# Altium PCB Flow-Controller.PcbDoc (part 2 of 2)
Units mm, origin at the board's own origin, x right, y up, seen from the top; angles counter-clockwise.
Board outline 85 x 90 mm, 2 copper layers (Top Layer, Bottom Layer), stack 1.571 mm thick; 113 components, 85 nets, 341 pads, 150 vias.
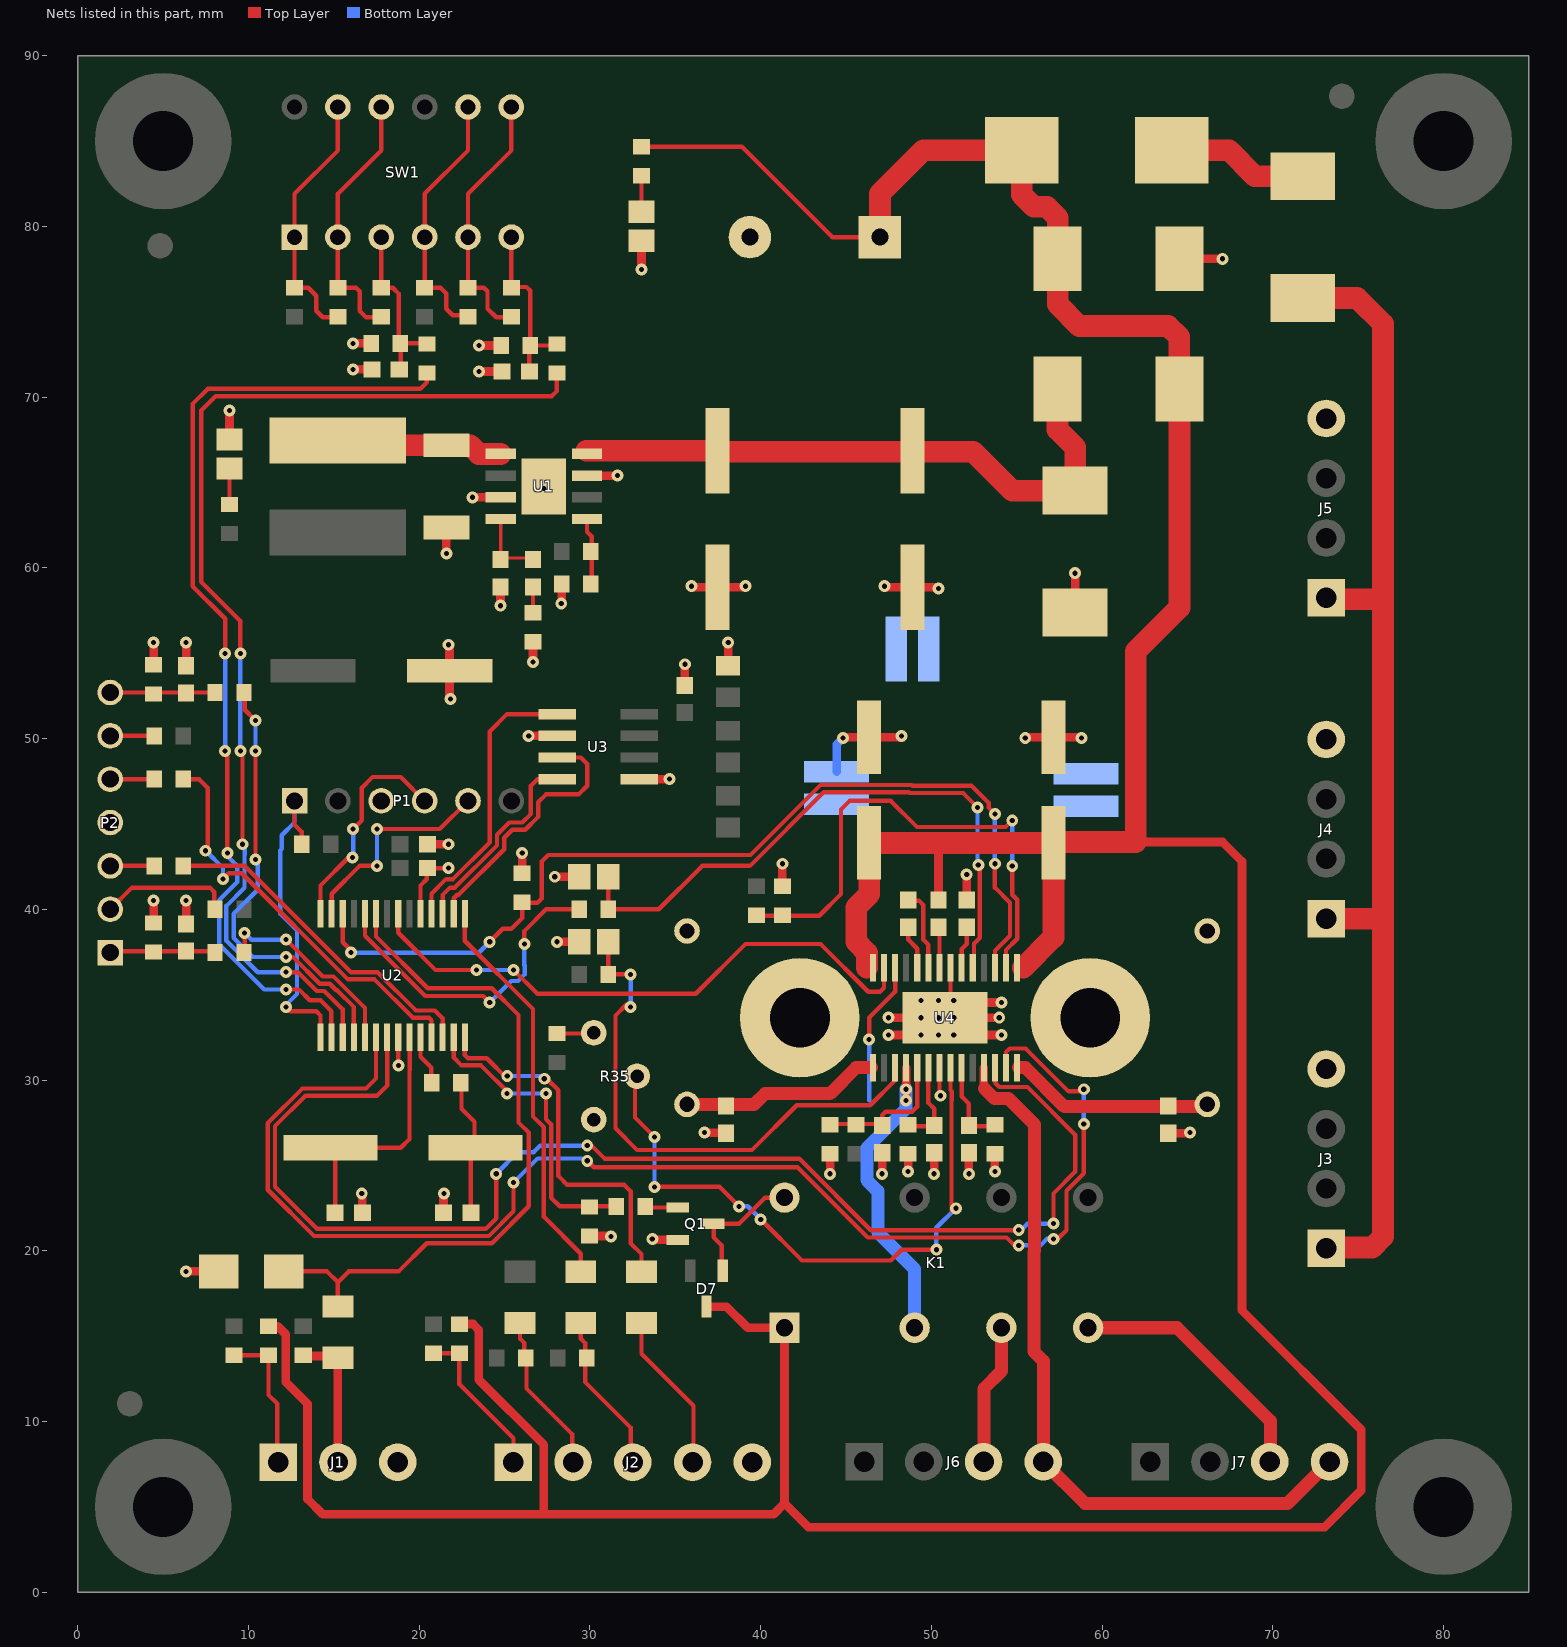
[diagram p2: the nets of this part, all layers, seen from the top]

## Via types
v1: diameter 0.7, hole 0.3, Top Layer to Bottom Layer, tented both sides, 150 vias

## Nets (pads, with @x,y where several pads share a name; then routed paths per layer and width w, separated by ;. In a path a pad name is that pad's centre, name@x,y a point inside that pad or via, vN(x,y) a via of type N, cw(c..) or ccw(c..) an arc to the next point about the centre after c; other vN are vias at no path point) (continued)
GND1: C1.2 C16.2 C17.2 C21.2 D4.2 HS1.1 HS1.2 J3.4 J4.4 J5.4 LED1.1 LK1.1 LK2.1 LK3.1 U4.21 U4.29 | length 39.2
  Top Layer w0.254: U4.29@51.125,33.853 51.125,34.488 U4.21@51.125,36.572
  Top Layer w0.508: v1(33.02,77.47) LED1.1@33.02,79.16 ; v1(44.831,50.038) 44.883,50.09 C16.2@46.355,50.09 48.185,50.09 v1(48.26,50.165) ; v1(47.498,32.639) 48.387,32.639 v1(49.403,33.655) ; v1(47.498,33.655) v1(49.403,33.655) ; v1(49.403,32.639) 49.784,32.639 U4.29@50.8,33.655 ; v1(49.403,34.671) 49.784,34.671 50.102,34.353 U4.29@50.8,33.655 ; v1(50.419,32.639) 50.8,33.02 U4.29@50.8,33.147 ; v1(50.419,34.671) 50.8,34.29 U4.29@50.8,34.163 ; v1(51.308,32.639) U4.29@50.8,33.147 ; v1(51.308,34.671) 51.125,34.488 U4.29@50.8,34.163 ; C21.2@52.07,40.551 v1(52.07,42.037) ; v1(53.975,33.655) U4.29@51.689,33.655 ; v1(54.102,32.639) 52.705,32.639 U4.29@51.689,33.655 ; v1(54.102,34.544) 52.578,34.544 U4.29@51.689,33.655 ; v1(55.499,50.038) 55.551,50.09 C17.2@57.15,50.09 58.749,50.09 v1(58.801,50.038) ; D4.2@64.53,78.105 v1(67.056,78.105) ; v1(49.403,33.655) v1(50.419,33.655) U4.29@50.8,33.655 ; U4.29@50.8,33.147 U4.29@50.8,33.655 ; U4.29@50.8,33.655 U4.29@50.8,34.163 ; U4.29@50.8,33.655 v1(51.308,33.655) U4.29@51.689,33.655
  Bottom Layer w0.508: LK2.1@44.45,48.069 44.45,49.657 v1(44.831,50.038)
GND2: C2.2 C3.2 C4.2 C6.2 C7.2 C8.2 C9.2 C10.2 C11.2 C12.2 C13.2 C14.2 C15.2 C20.2 C24.2 C25.2 C26.2 C27.2 D5.2 D6.2 J1.3 J2.5 LED2.1 LK1.2 P1.3 P2.4 Q1.2 R4.2 R5.2 R13.2 R30.2 R31.2 R32.2 R35.3 R36.2 R38.2 R41.2 R42.2 R48.2 R49.2 R54.2 U1.3 U1.7 U1.9 U2.8 U2.19 U3.2 U3.5 U4.7 U4.26 Z1.2 | length 74.6
  Top Layer w0.254: U2.8@18.774,32.512 18.774,30.883 v1(18.796,30.861) ; U2.19@20.074,39.751 20.074,41.394 20.447,41.767 20.447,42.291 20.574,42.418 v1(21.717,42.418) ; v1(46.355,32.385) 46.355,33.655 47.875,35.175 U4.26@47.875,36.572 ; U4.7@50.475,30.73 50.475,29.154 v1(50.546,29.083)
  Top Layer w0.508: R32.2@4.445,39.204 v1(4.445,40.513) ; R31.2@4.445,54.317 v1(4.445,55.626) ; v1(6.35,18.796) 6.352,18.794 Z1.2@8.255,18.794 ; C14.2@6.35,39.154 v1(6.35,40.513) ; C13.2@6.35,54.267 v1(6.35,55.626) ; LED2.1@8.89,67.525 v1(8.89,69.215) ; v1(16.129,71.628) C26.2@17.234,71.628 ; v1(16.129,73.152) R49.2@17.184,73.152 ; v1(16.637,23.368) 16.675,23.33 C10.2@16.675,22.225 ; C12.2@20.485,43.815 v1(21.717,43.815) ; C9.2@21.425,22.225 21.425,23.33 v1(21.463,23.368) ; v1(21.59,60.833) D6.2@21.59,62.357 ; v1(21.717,55.499) 21.78,55.436 C4.2@21.78,53.975 21.78,52.388 v1(21.844,52.324) ; v1(23.114,64.135) U1.3@24.778,64.135 ; v1(23.495,71.501) C27.2@24.854,71.501 ; v1(23.495,73.025) R54.2@24.804,73.025 ; v1(24.765,57.785) C6.2@24.765,58.89 ; R13.2@26.035,42.125 v1(26.035,43.307) ; v1(26.416,50.165) U3.2@28.08,50.165 ; v1(26.67,54.483) R4.2@26.67,55.665 ; v1(27.305,64.643) U1.9@27.305,64.77 ; v1(27.94,41.91) C7.2@29.376,41.91 ; v1(28.067,38.1) C8.2@29.376,38.1 ; v1(28.321,57.912) 28.36,57.951 R5.2@28.36,59.055 ; U1.7@29.832,65.405 v1(31.623,65.405) ; R48.2@29.972,20.867 31.203,20.867 v1(31.242,20.828) ; U3.5@32.88,47.625 v1(34.671,47.625) ; v1(33.655,20.701) 33.716,20.64 Q1.2@35.145,20.64 ; C15.2@35.56,53.124 v1(35.56,54.356) ; v1(35.941,58.928) 36.004,58.865 C3.2@37.465,58.865 39.053,58.865 v1(39.116,58.928) ; R30.2@38.1,54.265 v1(38.1,55.626) ; R36.2@41.275,41.363 v1(41.275,42.672) ; v1(44.069,24.511) R38.2@44.069,25.693 ; v1(47.117,24.511) C20.2@47.117,25.743 ; v1(47.244,58.928) 47.307,58.865 C2.2@48.895,58.865 50.355,58.865 v1(50.419,58.801) ; v1(48.641,24.638) R41.2@48.641,25.693 ; v1(50.165,24.511) C24.2@50.165,25.743 ; v1(52.197,24.511) C25.2@52.197,25.743 ; v1(53.721,24.638) R42.2@53.721,25.693 ; D5.2@58.42,57.39 v1(58.42,59.69)
  Bottom Layer w0.254: 46.355,28.829 v1(46.355,32.385)
GND3: C22.2 LK2.2 R39.1 | length 1.3
  Top Layer w0.508: v1(36.703,26.924) 37.935,26.924 C22.2@37.973,26.886
GND4: C23.2 LK3.2 R40.1 | length 1.3
  Top Layer w0.508: C23.2@63.881,26.886 65.113,26.886 v1(65.151,26.924)
GREEN: J6.4 J7.4 U4.11 | length 44
  Top Layer w0.254: J6.4@56.515,7.62 J6.4@56.515,7.645
  Top Layer w0.508: 53.075,29.348 U4.11@53.075,30.73
  Top Layer w0.762: 53.103,29.508 53.698,28.913 54.53,28.913 56.05,27.393 56.05,19.978 56.009,19.937 56.009,14.095 56.558,13.546 J6.4@56.558,7.645 58.996,5.207 70.866,5.207 J7.4@73.279,7.62
GREEN_LED: R27.1 U2.12 | length 20
  Top Layer w0.254: R27.1@6.223,42.545 9.779,42.545 16.002,36.322 17.561,36.322 19.806,34.077 20.914,34.077 21.374,33.617 U2.12@21.374,32.512
M_0: R24.1 U2.4 | length 25.9
  Top Layer w0.254: R24.1@9.779,52.832 9.779,51.689 v1(10.414,51.054) ; v1(10.414,42.926) v1(10.414,49.276) ; v1(12.192,37.211) 12.608,37.211 14.175,35.644 14.765,35.644 15.148,35.26 15.194,35.26 16.174,34.28 U2.4@16.174,32.512
  Bottom Layer w0.254: v1(10.414,42.926) 10.541,42.799 10.541,41.148 9.132,39.739 9.132,38.34 10.261,37.211 v1(12.192,37.211) ; v1(10.414,49.276) v1(10.414,51.054)
M_1: R29.1 U2.5 | length 11.7
  Top Layer w0.254: R29.1@9.779,37.465 v1(9.779,38.608) ; v1(12.192,38.227) 14.351,36.068 14.986,36.068 16.824,34.23 U2.5@16.824,32.512
  Bottom Layer w0.254: v1(9.779,38.608) 10.16,38.227 v1(12.192,38.227)
MCLR: P1.1 R6.2 U2.1 | length 19.3
  Top Layer w0.254: v1(12.192,34.29) 12.448,34.034 13.97,34.034 14.224,33.78 U2.1@14.224,32.512 ; P1.1@12.7,46.355 12.7,44.958 13.12,44.538 R6.2@13.12,43.815
  Bottom Layer w0.254: v1(12.192,34.29) 12.192,34.391 12.839,35.038 12.839,38.766 11.854,39.751 11.854,43.451 11.95,43.547 11.95,44.335 12.7,45.085 P1.1@12.7,46.355
MS_1: U2.6 U4.13 | length 82.3
  Top Layer w0.254: U2.6@17.474,32.512 17.474,30.09 16.891,29.507 13.159,29.507 11.133,27.481 11.133,23.573 13.835,20.871 24.081,20.871 25.527,22.317 v1(25.527,24.003) ; v1(29.845,25.273) 30.226,24.892 42.164,24.892 46.271,20.785 54.399,20.785 54.864,20.32 v1(55.118,20.32) ; U4.13@54.375,30.73 54.375,31.642 54.588,31.855 55.521,31.855 58.039,29.337 58.801,29.337 v1(58.928,29.464) ; v1(57.15,20.701) 57.404,20.701 57.912,21.209 57.912,23.521 58.928,24.537 v1(58.928,27.432)
  Bottom Layer w0.254: v1(25.527,24.003) 26.936,25.412 29.706,25.412 v1(29.845,25.273) ; v1(55.118,20.32) 56.388,20.32 56.769,20.701 v1(57.15,20.701) ; v1(58.928,27.432) v1(58.928,29.464)
MS_2: U2.7 U4.12 | length 78
  Top Layer w0.254: U2.7@18.124,32.512 18.124,29.681 17.526,29.083 13.335,29.083 11.557,27.305 11.557,23.749 14.011,21.295 23.906,21.295 24.511,21.9 v1(24.511,24.511) ; v1(29.845,26.162) 30.099,26.162 30.861,25.4 42.256,25.4 46.447,21.209 v1(55.118,21.209) ; 53.725,29.845 53.979,29.591 55.626,29.591 58.42,26.797 58.42,24.629 57.15,23.359 v1(57.15,21.59)
  Bottom Layer w0.254: v1(24.511,24.511) 25.781,25.781 26.705,25.781 27.086,26.162 v1(29.845,26.162) ; v1(55.118,21.209) 55.245,21.209 55.626,21.59 v1(57.15,21.59)
NetC5_1: C5.1 C6.1 U1.4 | length 4.2
  Top Layer w0.2: U1.4@24.778,62.865 24.778,60.592 24.791,60.579 C5.1@26.67,60.579
NetC5_2: C5.2 R4.1 | length 1.4
  Top Layer w0.254: R4.1@26.67,57.531 C5.2@26.67,58.89
NetC7_1: C7.1 R11.2 U4.19 | length 36.8
  Top Layer w0.2: 52.483,38.008 52.815,38.339
  Top Layer w0.254: C7.1@31.076,41.822 R11.2@31.076,40.005 34.036,40.005 36.576,42.545 39.37,42.545 43.688,46.863 48.676,46.863 48.719,46.82 51.859,46.82 v1(52.705,45.974) ; U4.19@52.425,36.572 52.494,36.641 52.494,37.98 52.842,38.328 v1@52.842,42.505 ; v1(52.749,42.589) v1@52.832,42.505
  Bottom Layer w0.254: v1(52.705,45.974) 52.705,42.632 v1(52.749,42.589)
NetC8_1: C8.1 R12.2 U4.3 | length 32.4
  Top Layer w0.254: R12.2@30.861,36.195 R12.2@31.076,36.195 ; C8.1@31.076,38.061 R12.2@31.076,36.195 ; v1(32.385,34.29) 32.258,34.417 32.131,34.417 31.496,33.782 31.496,27.178 32.766,25.908 39.497,25.908 42.121,28.532 46.425,28.532 47.875,29.982 U4.3@47.875,30.73 ; v1(32.385,36.195) R12.2@31.076,36.195
  Bottom Layer w0.254: v1(32.385,34.29) v1(32.385,36.195)
NetC9_1: C9.1 R14.1 X1.1 | length 7.9
  Top Layer w0.254: R14.1@22.479,29.845 22.479,28.321 23.241,27.559 X1.1@23.241,26.035 ; C9.1@23.025,22.225 X1.1@23.025,25.997
NetC10_1: C10.1 U2.9 X1.2 | length 14.1
  Top Layer w0.254: C10.1@15.075,22.225 X1.2@15.075,25.819 ; X1.2@15.113,26.035 18.923,26.035 19.431,26.543 19.431,30.562 19.443,30.574 19.443,32.493 U2.9@19.424,32.512
NetC13_1: C13.1 P2.7 R24.2 R31.1 | length 6.1
  Top Layer w0.254: P2.7@1.905,52.705 R24.2@8.001,52.705
NetC14_1: C14.1 P2.1 R29.2 R32.1 | length 6.2
  Top Layer w0.254: P2.1@1.994,37.554 C14.1@6.35,37.554 R29.2@8.166,37.554
NetC18_2: C18.2 U4.22 | length 2.4
  Top Layer w0.254: U4.22@50.475,36.572 C18.2@50.475,38.933
NetC19_1: C19.1 U4.24 | length 2.5
  Top Layer w0.254: C19.1@48.641,38.862 48.641,38.227 49.175,37.693 U4.24@49.175,36.572
NetC19_2: C19.2 U4.23 | length 4.7
  Top Layer w0.254: C19.2@48.768,40.513 49.276,40.513 49.53,40.259 49.53,38.227 49.825,37.932 U4.23@49.825,36.572
NetC20_1: C20.1 R37.2 R38.1 U4.5 | length 8.1
  Top Layer w0.254: R38.1@44.069,27.432 47.117,27.432 47.117,27.94 47.32,28.143 48.838,28.143 48.841,28.14 ; 48.816,28.14 48.841,28.14 ; U4.5@49.175,30.73 49.175,28.445 48.87,28.14 48.841,28.14
NetC21_1: C21.1 U4.20 | length 2.4
  Top Layer w0.254: U4.20@51.775,36.572 51.775,37.678 52.07,37.973 C21.1@52.07,38.862
NetC22_1: C22.1 R39.2 U4.1 | length 11.7
  Top Layer w0.762: R39.2@35.687,28.575 39.624,28.575 40.259,29.21 44.069,29.21 45.593,30.734 U4.1@46.482,30.734
NetC23_1: C23.1 R40.2 U4.14 | length 12.1
  Top Layer w0.762: U4.14@55.104,30.734 55.499,30.734 57.785,28.448 66.04,28.448 R40.2@66.167,28.575
NetC24_1: C24.1 R41.1 U4.6 | length 5.1
  Top Layer w0.254: R41.1@48.641,27.432 48.768,27.305 50.165,27.305 C24.1@50.165,27.343 50.165,28.321 49.825,28.661 U4.6@49.825,30.73
NetC25_1: C25.1 R42.1 U4.9 | length 5.2
  Top Layer w0.254: U4.9@51.775,30.73 51.775,29.032 52.197,28.61 C25.1@52.197,27.343 52.197,27.305 53.594,27.305 R42.1@53.721,27.432
NetC26_1: C26.1 R45.2 R47.2 R49.1 SW1.3 | length 10.2
  Top Layer w0.254: SW1.3@17.78,79.375 R45.2@17.78,76.415 18.454,76.415 18.796,76.073 18.796,73.152 18.923,73.025 C26.1@18.923,71.628 ; R49.1@18.884,73.152 R47.2@20.447,73.152
NetC27_1: C27.1 R52.2 R53.2 R54.1 SW1.6 | length 9.7
  Top Layer w0.254: R52.2@25.4,76.415 SW1.6@25.4,79.121 ; R52.2@25.527,76.454 26.289,76.454 26.504,76.239 R54.1@26.504,73.025 R53.2@27.813,73.025 ; C27.1@26.454,71.501 R54.1@26.454,72.936
NetD1_1: D1.1 D3.1 | length 8.4
  Top Layer w1.27: D3.1@64.008,84.455 D3.1@64.09,84.455 67.437,84.455 68.947,82.945 D1.1@71.755,82.945
NetD6_1: D6.1 L1.1 U1.1 | length 9.7
  Top Layer w1.27: L1.1@15.24,67.183 D6.1@21.59,67.183 22.987,67.183 23.495,66.675 U1.1@24.778,66.675
NetD7_1: D7.1 K1.16 Q1.3 | length 7.8
  Top Layer w0.254: D7.1@37.719,18.796 37.719,20.32 37.245,20.794 Q1.3@37.245,21.59 38.735,21.59 40.259,23.114 K1.16@41.402,23.114
NetJ1_1: J1.1 R8.2 R9.2 | length 8.5
  Top Layer w0.254: R8.2@9.183,13.882 R9.2@11.176,13.882 11.176,11.557 11.684,11.049 J1.1@11.684,7.62
NetJ1_2: J1.2 R7.2 R10.2 | length 8.1
  Top Layer w0.508: R7.2@13.208,13.843 14.986,13.843 15.24,13.589 J1.2@15.24,7.62
NetJ2_1: J2.1 R17.2 R18.2 | length 9.7
  Top Layer w0.254: R17.2@20.828,14.009 R18.2@22.352,14.009 R18.2@22.694,14.009 ; R18.2@22.352,13.97 22.352,12.192 25.527,9.017 J2.1@25.527,7.493
NetJ2_2: J2.2 R16.2 R19.2 | length 9.5
  Top Layer w0.254: R19.2@25.908,15.772 25.908,14.859 26.162,14.605 26.162,13.716 26.289,13.589 26.289,11.938 28.956,9.271 J2.2@28.956,7.493
NetJ2_3: J2.3 R15.2 R20.2 | length 9.4
  Top Layer w0.254: R20.2@29.464,15.772 29.464,14.859 29.718,14.605 29.718,12.319 32.385,9.652 J2.3@32.385,7.62
NetJ2_4: J2.4 R21.2 | length 9.4
  Top Layer w0.254: R21.2@33.02,15.772 33.02,13.97 36.068,10.922 J2.4@36.068,7.62
NetLED1_2: LED1.2 R1.2 | length 2.1
  Top Layer w0.254: LED1.2@33.02,80.86 R1.2@33.02,82.931
NetLED2_2: LED2.2 R2.2 | length 1.9
  Top Layer w0.254: R2.2@8.89,63.715 LED2.2@8.89,65.659
NetP2_2: P2.2 R26.2 | length 7.7
  Top Layer w0.254: P2.2@1.905,40.005 3.175,41.275 7.747,41.275 8.001,41.021 R26.2@8.001,40.005
NetP2_3: P2.3 R27.2 | length 2.5
  Top Layer w0.254: P2.3@2.032,42.545 R27.2@4.484,42.545
NetP2_5: P2.5 R28.2 | length 2.5
  Top Layer w0.254: P2.5@2.032,47.625 R28.2@4.484,47.625
NetP2_6: P2.6 R25.2 | length 2.3
  Top Layer w0.254: P2.6@2.159,50.165 R25.2@4.484,50.165
NetQ1_1: Q1.1 R46.2 | length 1.8
  Top Layer w0.254: R46.2@33.335,22.54 Q1.1@35.145,22.54
NetR3_2: R3.2 R5.1 U1.5 | length 4
  Top Layer w0.254: U1.5@29.832,62.865 29.832,62.116 30.099,61.849 R5.1@30.099,58.928
NetR14_2: R14.2 U2.10 | length 2.9
  Top Layer w0.254: U2.10@20.074,32.512 20.074,31.361 20.701,30.734 R14.2@20.701,29.845
NetR33_2: R33.2 R36.1 U4.16 | length 30.6
  Top Layer w0.254: R33.2@39.624,39.624 43.434,39.624 44.704,40.894 44.704,45.847 45.212,46.355 47.625,46.355 49.158,44.822 54.347,44.822 v1(54.737,45.212) ; U4.16@54.375,36.572 54.375,37.62 55.034,38.279 55.034,40.562 54.737,40.859 v1(54.737,42.545)
  Bottom Layer w0.254: v1(54.737,42.545) v1(54.737,45.212)
NetR34_2: R34.2 R35.1 | length 2.2
  Top Layer w0.254: R34.2@28.067,32.727 R35.1@30.265,32.727
NetR35_2: R35.2 U4.8 | length 37.1
  Top Layer w0.254: R35.2@32.639,30.226 32.639,27.813 v1(33.782,26.67) ; v1(33.782,23.749) 37.592,23.749 v1(38.735,22.606) ; v1(40.005,21.844) 42.418,19.431 47.625,19.431 48.26,20.066 v1(50.292,20.066) ; U4.8@51.125,30.73 51.125,29.419 51.193,29.351 51.193,28.803 51.181,28.791 51.181,22.352 51.296,22.352 v1(51.435,22.491)
  Bottom Layer w0.254: v1(33.782,23.749) v1(33.782,26.67) ; v1(38.735,22.606) 39.243,22.606 v1(40.005,21.844) ; v1(50.292,20.066) 50.292,21.348 v1(51.435,22.491)
NetR43_2: R43.2 R44.1 SW1.1 SW1.11 | length 15.4
  Top Layer w0.254: R44.1@15.24,74.676 14.351,74.676 13.97,75.057 13.97,75.946 13.501,76.415 R43.2@12.7,76.415 SW1.1@12.7,79.375 12.7,81.915 15.24,84.455 SW1.11@15.24,86.995
NetR44_2: R44.2 R45.1 SW1.2 SW1.10 | length 15.6
  Top Layer w0.254: R45.1@17.78,74.676 16.891,74.676 16.51,75.057 16.51,76.2 16.295,76.415 R44.2@15.24,76.415 SW1.2@15.24,79.375 15.24,81.915 17.78,84.455 SW1.10@17.78,86.995
NetR46_1: R46.1 R48.1 U2.13 | length 18
  Top Layer w0.254: U2.13@22.024,32.512 22.024,31.316 22.479,30.861 23.622,30.861 25.273,29.21 v1(25.146,29.21) ; v1(27.432,29.21) 27.432,27.707 27.729,27.41 27.729,23.114 28.237,22.606 R46.1@31.535,22.606
  Bottom Layer w0.254: v1(25.146,29.21) v1(27.432,29.21)
NetR47_1: R47.1 U2.2 | length 57.8
  Top Layer w0.254: v1(8.636,49.276) 8.763,49.149 v1(8.763,43.307) ; v1(8.636,54.991) 8.636,57.023 6.731,58.928 6.731,69.596 7.62,70.485 20.066,70.485 20.447,70.866 R47.1@20.447,71.413 R47.1@20.447,71.501 ; v1(12.192,35.306) 12.954,35.306 13.589,34.671 14.224,34.671 14.859,34.036 U2.2@14.859,33.274 ; U2.2@14.874,32.512 U2.2@14.874,33.274
  Bottom Layer w0.254: v1(8.636,49.276) v1(8.636,54.991) ; v1(8.763,43.307) 8.763,43.125 9.343,42.545 9.343,41.601 8.284,40.542 8.284,37.944 10.922,35.306 v1(12.192,35.306)
NetR50_2: R50.2 R51.1 SW1.4 SW1.8 | length 15.5
  Top Layer w0.254: SW1.8@22.86,86.995 22.86,84.455 20.32,81.915 SW1.4@20.32,79.375 R50.2@20.32,76.415 21.248,76.415 21.59,76.073 21.59,75.184 21.971,74.803 R51.1@22.987,74.803
NetR51_2: R51.2 R52.1 SW1.5 SW1.7 | length 15.5
  Top Layer w0.254: R52.1@25.4,74.676 24.511,74.676 24.003,75.184 24.003,76.2 23.788,76.415 R51.2@22.86,76.415 SW1.5@22.86,79.375 22.86,81.915 25.4,84.455 SW1.7@25.4,86.995
NetR53_1: R53.1 U2.3 | length 65.2
  Top Layer w0.254: v1(9.525,49.276) 9.652,49.276 v1(9.652,43.815) ; v1(9.525,54.991) 9.525,56.896 7.239,59.182 7.239,69.215 8.085,70.061 27.77,70.061 28.067,70.358 R53.1@28.067,71.413 R53.1@28.067,71.501 ; v1(12.192,36.322) 12.898,36.322 14,35.22 14.437,35.22 15.494,34.163 ; U2.3@15.524,32.512 15.524,34.163
  Bottom Layer w0.254: v1(9.525,49.276) v1(9.525,54.991) ; v1(9.652,43.815) 9.779,43.688 9.779,43.218 9.767,43.206 9.767,41.263 8.708,40.204 8.708,38.164 10.55,36.322 v1(12.192,36.322)
PGC: P1.5 U2.27 | length 12.7
  Top Layer w0.254: U2.27@14.874,39.751 14.874,40.909 16.51,42.545 v1(17.526,42.545) ; v1(17.526,44.704) 21.209,44.704 P1.5@22.86,46.355
  Bottom Layer w0.254: v1(17.526,42.545) v1(17.526,44.704)
PGD: P1.4 U2.28 | length 13.1
  Top Layer w0.254: U2.28@14.224,39.751 14.224,41.402 15.875,43.053 16.103,43.053 v1(16.091,43.041) ; v1(16.129,44.704) 16.637,45.212 16.637,47.117 17.272,47.752 18.923,47.752 P1.4@20.32,46.355
  Bottom Layer w0.254: v1(16.091,43.041) 16.129,43.079 v1(16.129,44.704)
RED: K1.4 U4.4 | length 18
  Top Layer w0.254: v1(48.514,29.464) v1@48.525,29.475
  Top Layer w0.508: v1@48.525,28.84 48.525,29.475 U4.4@48.525,30.73
  Bottom Layer w0.762: v1(48.514,29.464) v1(48.514,28.804) 48.514,28.321 46.216,26.023 46.216,24.138 46.863,23.491 46.863,21.082 49.022,18.923 K1.4@49.022,15.494
RED_LED: R28.1 U2.11 | length 24.3
  Top Layer w0.254: R28.1@6.223,47.625 7.112,47.625 7.62,47.117 7.62,43.561 v1(7.493,43.434) ; v1(8.509,41.783) 8.847,42.121 9.603,42.121 15.826,35.898 17.386,35.898 19.631,33.653 20.576,33.653 20.724,33.505 U2.11@20.724,32.512
  Bottom Layer w0.254: v1(7.493,43.434) 8.509,42.418 v1(8.509,41.783)
RED_M1: J6.3 K1.6 | length 8.3
  Top Layer w0.762: J6.3@53.086,7.62 53.086,11.938 54.102,12.954 K1.6@54.102,15.494
RED_M2: J7.3 K1.8 | length 15.3
  Top Layer w0.762: K1.8@59.182,15.494 64.389,15.494 69.85,10.033 J7.3@69.85,7.62
RESET_A3979: R13.1 U2.26 U4.17 | length 56.9
  Top Layer w0.254: U2.26@15.524,39.751 15.524,38.07 16.129,37.465 v1(16.002,37.465) ; v1(24.13,38.1) 24.892,38.862 25.4,38.862 26.035,39.497 26.035,40.386 26.924,40.386 27.178,40.64 27.178,42.799 27.559,43.18 39.405,43.18 43.512,47.287 48.852,47.287 48.895,47.244 52.35,47.244 53.352,46.242 53.352,45.962 v1(53.721,45.593) ; v1(53.721,42.672) 53.721,41.275 54.61,40.386 54.61,38.455 53.725,37.57 U4.17@53.725,36.572
  Bottom Layer w0.254: v1(16.002,37.465) 23.495,37.465 v1(24.13,38.1) ; v1(53.721,42.672) v1(53.721,45.593)
RX: U2.18 U3.1 | length 16.5
  Top Layer w0.254: U2.18@20.724,39.751 20.724,40.917 21.578,41.771 21.985,41.771 24.13,43.916 24.13,50.419 25.146,51.435 U3.1@27.94,51.435
SCL: R21.1 U2.14 | length 22
  Top Layer w0.254: U2.14@22.674,32.512 22.674,31.471 22.86,31.285 23.96,31.285 25.146,30.099 25.146,30.226 v1(25.159,30.239) ; v1(27.329,30.08) 27.477,30.08 28.153,29.404 28.153,24.384 28.661,23.876 32.004,23.876 32.385,23.495 32.385,20.447 33.02,19.812 R21.1@33.02,18.923
  Bottom Layer w0.254: v1(25.159,30.239) 27.17,30.239 v1(27.329,30.08)
SDA: R20.1 U2.15 | length 23.9
  Top Layer w0.254: U2.15@22.674,39.751 22.674,38.159 26.67,34.163 26.67,27.869 27.305,27.234 27.305,21.99 29.464,19.831 R20.1@29.464,18.772 R20.1@29.464,18.669
SENSOR: R10.1 U2.23 Z1.1 | length 40.9
  Top Layer w0.254: Z1.1@12.065,18.796 14.605,18.796 15.24,18.161 ; R10.1@15.24,16.74 15.24,18.161 ; U2.23@17.474,39.751 17.474,38.406 20.502,35.378 24.256,35.378 25.822,33.812 25.822,27.518 26.416,26.924 26.416,22.606 24.257,20.447 20.447,20.447 18.796,18.796 15.875,18.796 15.24,18.161
SLEEP: U2.21 U4.27 | length 34.7
  Top Layer w0.254: U2.21@18.774,39.751 18.774,38.63 20.955,36.449 v1(23.368,36.449) ; v1(25.527,36.449) 26.924,35.052 36.195,35.052 39.116,37.973 43.513,37.973 46.307,35.179 46.99,35.179 47.225,35.414 U4.27@47.225,36.572
  Bottom Layer w0.254: v1(23.368,36.449) v1(25.527,36.449)
STEP_A3979: R11.1 U2.24 | length 19.2
  Top Layer w0.254: U2.24@16.824,39.751 16.824,38.456 20.355,34.925 23.749,34.925 v1(24.13,34.544) ; v1(26.162,37.973) 26.162,38.735 27.432,40.005 R11.1@29.337,40.005
  Bottom Layer w0.254: v1(24.13,34.544) 25.388,35.802 25.795,35.802 26.174,36.181 26.174,36.729 26.162,36.741 v1(26.162,37.973)
TX: U2.17 U3.4 | length 11.8
  Top Layer w0.254: U2.17@21.374,39.751 21.374,40.84 21.809,41.275 22.089,41.275 24.554,43.74 24.554,44.366 25.273,45.085 26.035,45.085 26.543,45.593 26.543,47.244 26.924,47.625 U3.4@27.94,47.625
TX_EN: U2.16 U3.3 | length 15.4
  Top Layer w0.254: U2.16@22.024,39.751 22.024,40.65 22.225,40.851 22.309,40.851 24.978,43.52 24.978,44.19 25.449,44.661 26.211,44.661 26.967,45.417 26.967,46.271 27.432,46.736 29.337,46.736 29.845,47.244 29.845,48.514 29.464,48.895 U3.3@28.194,48.895
V+POWER: C1.1 C16.1 C17.1 C18.1 D2.2 D3.2 D4.1 D7.3 K1.1 R1.1 R9.1 R18.1 U4.15 U4.28 | length 262.4
  Top Layer w0.254: R1.1@33.02,84.67 38.901,84.67 44.196,79.375 C1.1@46.99,79.375
  Top Layer w0.508: R9.1@11.176,15.582 11.723,15.582 12.192,15.113 12.192,12.319 13.462,11.049 13.462,5.461 14.351,4.572 27.305,4.572 ; R18.1@22.352,15.709 23.153,15.709 23.495,15.367 23.495,12.446 27.305,8.636 27.305,4.572 ; D7.3@36.83,16.73 38.007,16.73 39.243,15.494 K1.1@41.402,15.494 41.402,5.207 ; C18.1@50.419,40.551 50.419,43.89 50.419,43.942 ; 61.976,43.942 67.056,43.942 68.199,42.799 68.199,16.51 75.184,9.525 75.184,5.969 73.025,3.81 42.799,3.81 41.402,5.207 ; 27.305,4.572 40.767,4.572 41.402,5.207
  Top Layer w1.27: 46.242,36.576 46.228,36.576 46.228,37.465 45.593,38.1 45.593,40.132 46.355,40.894 C16.1@46.355,43.89 50.419,43.89 C17.1@57.075,43.89 ; C1.1@46.99,79.375 46.99,81.915 49.53,84.455 D3.2@55.29,84.455 55.29,81.87 56.007,81.153 56.769,81.153 57.404,80.518 57.404,75.438 58.674,74.168 63.881,74.168 64.516,73.533 D2.2@64.516,70.612 ; 55.358,36.576 55.372,36.576 57.15,38.354 C17.1@57.15,43.89 ; C17.1@57.15,43.942 61.976,43.942 61.976,55.118 64.53,57.672 D2.2@64.53,70.485
VCC: C2.1 C3.1 D2.1 D5.1 U1.8 | length 35.9
  Top Layer w1.27: U1.8@29.782,66.865 C3.1@37.465,66.865 ; C3.1@37.592,66.802 52.451,66.802 54.737,64.516 58.42,64.516 D5.1@58.42,64.53 58.42,67.056 57.39,68.086 D2.1@57.39,70.485
VIN: D1.2 J3.1 J4.1 J5.1 | length 68.9
  Top Layer w1.27: D1.2@71.755,75.805 74.944,75.805 76.454,74.295 76.454,58.166 ; J4.1@73.127,39.454 76.37,39.454 ; J3.1@73.152,20.193 75.819,20.193 76.454,20.828 76.454,58.166 ; J5.1@73.152,58.166 76.454,58.166
pads on no net: D7.2 P1.6 U1.2 U1.6 U4.2

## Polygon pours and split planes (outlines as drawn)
GND1 on Bottom Layer "Bot - GND1a" (solid, pour order 14): 49.53,57.785 49.53,52.705 42.545,52.705 42.545,47.625 61.595,47.625 61.595,57.785
GND3 on Bottom Layer "Bot - GND3a" (solid, pour order 17): 42.545,46.355 46.355,46.355 46.355,43.18 42.545,43.18
GND4 on Bottom Layer "Bot - GND4a" (solid, pour order 18): 57.15,46.355 61.595,46.355 61.595,44.45 57.15,44.45
GND2 on Bottom Layer "Bot - GND2a" (solid, pour order 19): 48.26,58.42 48.26,53.34 46.355,53.34 46.355,58.42
GND3 on Bottom Layer "Bot - GND3" (solid, remove dead copper, pour order 11): 42.545,46.99 46.355,46.99 46.355,41.275 45.085,41.275 45.085,38.1 38.1,38.1 38.1,26.035 34.29,26.035 34.29,41.91 42.545,41.91
GND4 on Bottom Layer "Bot - GND4" (solid, pour order 12): 57.15,46.99 57.15,41.275 63.5,41.275 63.5,26.035 67.945,26.035 67.945,46.99
GND2 on Bottom Layer "Bot - GND2" (solid, remove dead copper, pour order 16): 1.27,88.9 30.48,88.9 30.48,69.85 61.595,69.85 61.595,58.42 48.26,58.42 48.26,53.34 41.91,53.34 41.91,42.545 33.655,42.545 33.655,25.4 38.735,25.4 38.735,29.21 62.865,29.21 62.865,25.4 67.945,25.4 67.945,15.875 83.82,15.875 83.82,0.635 1.27,0.635
GND1 on Bottom Layer "Bot - GND1" (solid, remove dead copper, pour order 13): 83.82,88.9 31.115,88.9 31.115,70.485 62.23,70.485 62.23,57.785 49.53,57.785 49.53,52.705 42.545,52.705 42.545,47.625 47.625,47.625 47.625,40.64 45.72,40.64 45.72,37.465 38.735,37.465 38.735,29.845 62.865,29.845 62.865,40.64 55.88,40.64 55.88,47.625 68.58,47.625 68.58,16.51 83.82,16.51
GND1 on Bottom Layer "Bot - GND1-HSK" (solid, remove dead copper, pour order 15): 38.735,37.465 38.735,29.845 62.865,29.845 62.865,37.465
GND1 on Top Layer "Top - GND1-HSK" (solid, remove dead copper, pour order 22): 53.721,35.179 53.721,32.258 56.007,32.258 56.388,31.877 58.42,29.845 62.865,29.845 62.865,40.64 58.42,40.64 58.42,35.179

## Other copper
Top Layer:
  text "TOP" at 2.159,25.654 h2 r90
Bottom Layer:
  text "BOTTOM" at 2.215,30.984 h2 r90

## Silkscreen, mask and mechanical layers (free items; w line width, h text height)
Top Overlay:
  lines w0.127: 27.432,58.166 27.813,57.785 ; 45.974,29.718 46.99,29.337 47.117,28.448 ; 50.165,28.321 51.181,29.337 53.975,29.464
Bottom Overlay:
  circle w0.2: c36.221,75.71 r1.75
  region: 21.223,57.69 21.516,56.983 22.223,56.69 35.473,56.69 36.18,56.983 36.473,57.69 36.473,59.94 36.18,60.647 35.473,60.94 22.223,60.94 21.516,60.647 21.223,59.94
  lines w0.3: 24.814,68.034 24.814,63.589 28.624,63.589 ; 24.814,68.039 28.624,68.039 32.434,68.039 36.244,68.039 ; 28.624,68.034 28.624,63.589 ; 32.434,68.034 32.434,63.589 ; 36.244,68.034 36.244,63.589 32.434,63.589 ; 28.624,63.589 32.434,63.589
  text "C    2011" at 36.815,74.951 h2
  text "AGRIGEL" at 55.245,74.168 h3.5
  text ".PCB_TITLE" at 55.088,71.042 h2.54
  text ".Version" at 55.088,67.792 h2.54
  text "MOD:" at 42.545,65.151 h2.25
  text "C" at 27.864,64.58 h3.5
  text "B" at 31.464,64.58 h3.5
  text "A" at 35.464,64.58 h3.5
  text "ISSUE:" at 43.688,57.785 h2.25
Board:
  the board outline again, w0.051
Mechanical 15:
  circle w0.025: c5,85 r2
  circle w0.025: c80,85 r2
  circle w0.025: c80,5 r2
  circle w0.025: c5,5 r2
  lines w0.051: 0,5 10,5 ; 0,85 10,85 ; 0.635,0.635 84.455,89.535 ; 0.635,89.535 84.455,0.635 ; 5,0 5,10 ; 5,80 5,90 ; 75,5 85,5 ; 75,85 85,85 ; 80,0 80,10 ; 80,80 80,90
